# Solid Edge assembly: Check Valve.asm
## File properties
Title: Check Valve Assembly
Author: Dan
Template: Normal.asm
Last saved by: Dan
Revision: 36
Application: Solid Edge
Project Name: Piston Pump P52
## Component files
Check Valve Housing.par
Ball Dia9.525.par
Check Valve Ball Stopper.par
Check Valve Spring.par
Dia10 Washer.par
Dia3 Sel lock Pin.par
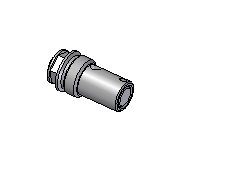
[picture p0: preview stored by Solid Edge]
